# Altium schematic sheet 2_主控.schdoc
size 431 x 309 mm; Symbol: Sheet-Symbol_A3; Device: Sheet-Symbol_A3; Company: 嘉立创EDA; Version: V1.0; Page Size: A3; @Project Name: 基于stm32和ttp233的触摸键盘; @Page Count: 3; @Update Date: 2024-11-03; @Create Date: 2024-11-03; @Schematic Name: Schematic1_1; @Page No: 2; @Page Name: 主控; Title Block Position: 3; Width: 1170; Height: 825; Region Start: 1; X Region Count: 6; Y Region Count: 4; Blade Width: 10; @Board Name: Board1; @Create Time: 21:01:00; @Update Time: 21:01:07
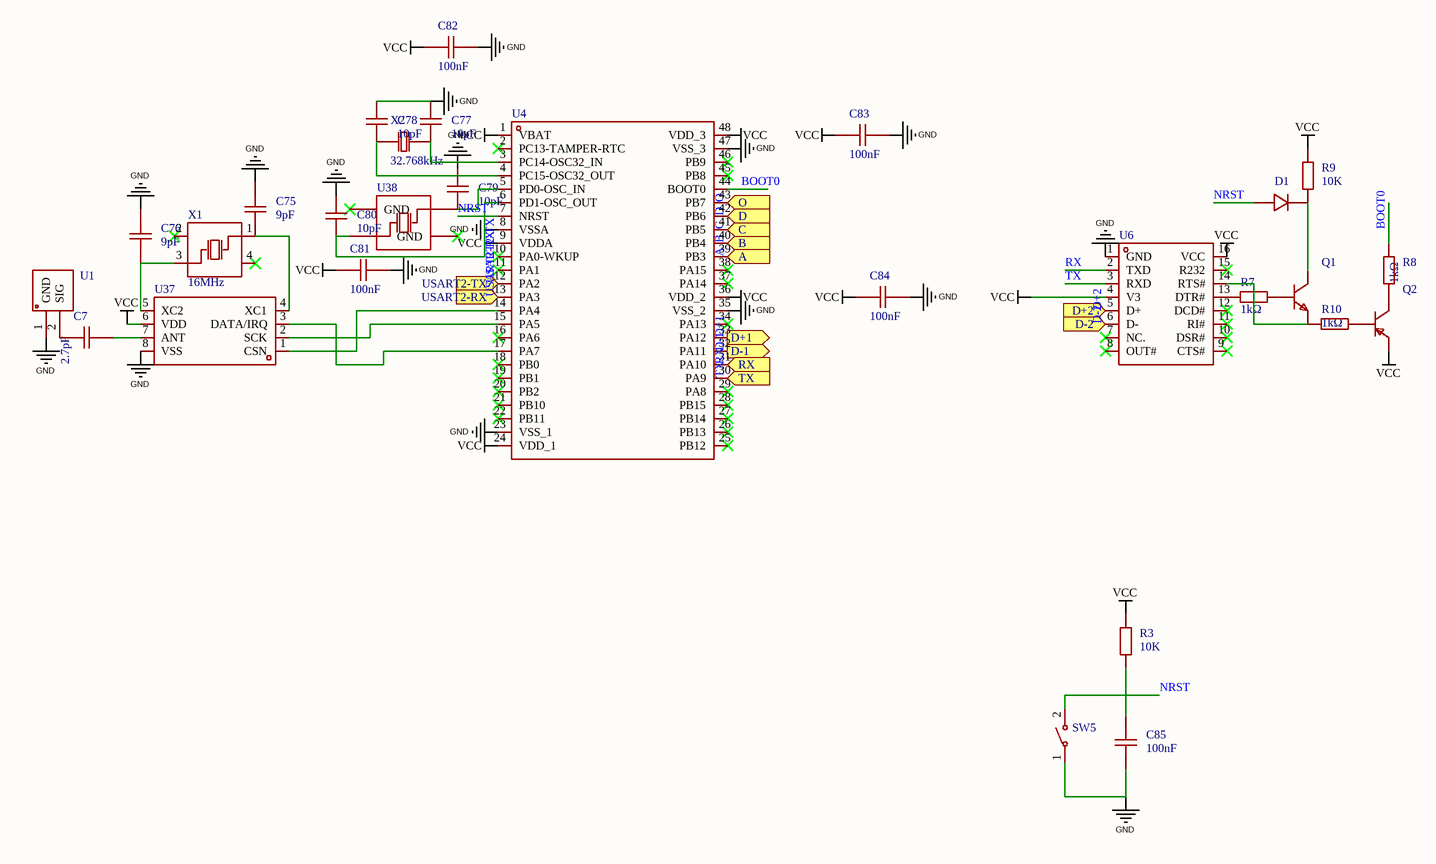
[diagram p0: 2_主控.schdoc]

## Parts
C7  2.7pF  [C0603]
C75  9pF  [C0603]
C76  9pF  [C0603]
C77  10pF  [C0603]
C78  10pF  [C0603]
C79  10pF  [C0603]
C80  10pF  [C0603]
C81  100nF  [C0603]
C82  100nF  [C0603]
C83  100nF  [C0603]
C84  100nF  [C0603]
C85  100nF  [C0603]  (value not drawn)
D1  1N4148W  [SOD-123F_L2.7-W1.6-LS3.8-RD]  (value not drawn)
Q1  S8050 J3Y  [SOT-23-3_L3.0-W1.7-P0.95-LS2.9-BR]  (value not drawn)
Q2  S8550-2TY 800MA  [SOT-23-3_L2.9-W1.6-P1.90-LS2.8-BR]  (value not drawn)
R3  10K  [R0603]  (value not drawn)
R7  1kΩ  [R0603]
R8  1kΩ  [R0603]
R9  10K  [R0603]  (value not drawn)
R10  1kΩ  [R0603]
SW5  TS-1088R-02526  [SW-SMD_L3.9-W3.0-P4.45]  (value not drawn)
U1  板载天线  [板载天线]  (value not drawn)
U4  STM32F103C8T6  [LQFP-48_L7.0-W7.0-P0.50-LS9.0-BL]  (value not drawn)
U6  CH340C  [SOP-16_L10.0-W3.9-P1.27-LS6.0-BL]  (value not drawn)
U37  Ci24R1  [SOIC-8_L4.9-W3.9-P1.27-LS6.0-BL]  (value not drawn)
U38  SMD_3225-8MHz  [CRYSTAL-SMD_4P-L3.2-W2.5-BL]  (value not drawn)
X1  16MHz  [OSC-SMD_4P-L3.2-W2.5-BL]
X2  32.768kHz  [FC-135R_L3.2-W1.5]

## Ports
A (in), B (in), C (in), D (in), D+1 (out), D+2 (in), D-1 (out), D-2 (in), O (in), RX (in), TX (in), USART2-RX (in), USART2-TX (in)

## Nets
GND: C75.2 C76.1 C77.2 C78.2 C79.2 C80.2 C81.1 C82.1 C83.1 C84.1 C85.1 SW5.1 U1.1(GND) U4.8(VSSA) U4.23(VSS_1) U4.35(VSS_2) U4.47(VSS_3) U6.1(GND) U37.8(VSS)
VCC: C81.2 C82.2 C83.2 C84.2 Q2.2(E) R3.2 R9.2 U4.1(VBAT) U4.9(VDDA) U4.24(VDD_1) U4.36(VDD_2) U4.48(VDD_3) U6.4(V3) U6.16(VCC) U37.6(VDD)
A: U4.39(PB3) ; port A
B: U4.40(PB4) ; port B
BOOT0: R8.2 U4.44(BOOT0)
C: U4.41(PB5) ; port C
D: U4.42(PB6) ; port D
D+1: U4.33(PA12) ; port D+1
D+2: U6.5(D+) ; port D+2
D-1: U4.32(PA11) ; port D-1
D-2: U6.6(D-) ; port D-2
NRST: C85.2 D1.2(A) R3.1 SW5.2 U4.7(NRST)
O: U4.43(PB7) ; port O
RX: U4.31(PA10) U6.2(TXD) ; port RX
TX: U4.30(PA9) U6.3(RXD) ; port TX
USART2-RX: U4.13(PA3) ; port USART2-RX
USART2-TX: U4.12(PA2) ; port USART2-TX
NetC7_1: C7.1 U37.7(ANT)
NetC7_2: C7.2 U1.2(SIG)
NetC75_1: C75.1 U37.4(XC1) X1.1(OSC1)
NetC76_2: C76.2 U37.5(XC2) X1.3(OSC2)
NetC77_1: C77.1 U4.3(PC14-OSC32_IN) X2.1
NetC78_1: C78.1 U4.4(PC15-OSC32_OUT) X2.2
NetC79_1: C79.1 U4.5(PD0-OSC_IN) U38.1(OSC1)
NetC80_1: C80.1 U4.6(PD1-OSC_OUT) U38.3(OSC2)
NetD1_1: D1.1(K) Q1.3(C) R9.1
NetQ1_1: Q1.1(B) R7.2
NetQ1_2: Q1.2(E) R10.1 U6.14(RTS#)
NetQ2_1: Q2.1(B) R10.2
NetQ2_3: Q2.3(C) R8.1
NetR7_1: R7.1 U6.13(DTR#)
NetU4_14: U4.14(PA4) U37.1(CSN)
NetU4_15: U4.15(PA5) U37.2(SCK)
NetU4_17: U4.17(PA7) U37.3(DATA/IRQ)

Not connected (* = marked no-connect by the designer): U4 2(PC13-TAMPER-RTC)* 10(PA0-WKUP)* 11(PA1)* 16(PA6)* 18(PB0)* 19(PB1)* 20(PB2)* 21(PB10)* 22(PB11)* 25(PB12)* 26(PB13)* 27(PB14)* 28(PB15)* 29(PA8)* 34(PA13)* 37(PA14)* 38(PA15)* 45(PB8)* 46(PB9)*; U6 7(NC.)* 8(OUT#)* 9(CTS#)* 10(DSR#)* 11(RI#)* 12(DCD#)* 15(R232)*; U38 2(GND)* 4(GND)*; X1 2(GND)* 4(GND)*

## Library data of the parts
C7 = 2.7pF(2R7) ±0.25pF 50V: 容值:2.7pF;额定电压:50V;材质(温度系数):-;; Manufacturer: SAMSUNG(三星); Symbol: 2.7PF(2R7)-±0.25PF-50V; Add into BOM: yes; Voltage Rated: 50V
C75 C76 = CC0603CRNPO9BN9R0: 容值:9pF;额定电压:50V;材质(温度系数):NP0;; Manufacturer: YAGEO(国巨); Add into BOM: yes; Voltage Rated: 50V; Temperature Coefficient: NP0
C77-C80 = CL10C100JB8NNNC: 容值:10pF;精度:±5%;额定电压:50V;材质(温度系数):C0G;; Manufacturer: SAMSUNG(三星); Add into BOM: yes; Tolerance: ±5%; Voltage Rated: 50V; Temperature Coefficient: C0G
C81-C84 = CC0603KRX7R9BB104: 容值:100nF;精度:±10%;额定电压:50V;材质(温度系数):X7R;; Manufacturer: YAGEO(国巨); Add into BOM: yes; Tolerance: ±10%; Voltage Rated: 50V; Temperature Coefficient: X7R
C85 = CAP_0603: Symbol: CapAcitance; Convert to PCB: yes
D1 = 1N4148W_C81598: 二极管配置:独立式;正向压降(Vf):1V@50mA;直流反向耐压(Vr):75V;平均整流电流(Io):150mA;功率:400mW;反向恢复时间(trr):4ns;; Manufacturer: ST(先科); Add into BOM: yes; Diode Configuration: 独立式; Reverse Voltage (Vr): 75V; Average Rectified Current (Io): 150mA; Power Dissipation: 400mW; Reverse Leakage Current: 1uA@75V; Reverse Recovery Time (trr): 4ns
Q1 = S8050 J3Y_C2146: 晶体管类型:NPN;集电极电流(Ic):500mA;集射极击穿电压(Vceo):25V;功率(Pd):300mW;直流电流增益(hFE@Ic,Vce):200@50mA,1V;; Manufacturer: CJ(江苏长电/长晶); Symbol: S8050_C2146; Add into BOM: yes; Transistor Type: NPN; Collector Current (Ic): 500mA; Collector-Emitter Breakdown Voltage (Vceo): 25V; Power Dissipation (Pd): 300mW; Transition Frequency (fT): 150MHz; Collector Cut-Off Current (Icbo): 100nA; Collector-Emitter Saturation Voltage (VCE(sat)@Ic,Ib): 600mV@500mA,50mA
Q2 = S8550-2TY 800MA: Manufacturer: IDCHIP(英锐芯); Add into BOM: yes
R3 R9 = Res_0603: Symbol: 电阻; Convert to PCB: yes
R7 R8 R10 = 0603WAF1001T5E: 电阻类型:厚膜电阻;阻值:1kΩ;精度:±1%;功率:100mW;最大工作电压:75V;温度系数:±100ppm/℃;; Manufacturer: UNI-ROYAL(厚声); Add into BOM: yes; Tolerance: ±1%; Power(Watts): 100mW; Overload Voltage (Max): 75V
SW5 = TS-1088R-02526: 电路结构:单刀单掷;按钮形状:圆形按钮;安装方式:立贴;开关长度:3.9mm;开关宽度:2.93mm;开关高度:2.5mm;触点电流:50mA;额定电压(DC):12V;带灯:-;机械寿命:-;; Manufacturer: XUNPU(讯普); Add into BOM: yes; Circuit: 单刀单掷; Actuator Style: 圆形按钮; Switch Length: 3.9mm; Switch Width: 2.93mm; Switch Height: 2.5mm; Contact Current: 50mA; Voltage Rating (DC): 12V
U1 = 板载天线: Add into BOM: yes
U4 = STM32F103C8T6: CPU内核:ARM-M3;程序存储容量:64KB;RAM总容量:20KB;GPIO端口数量:37;工作电压范围:2V~3.6V;CPU最大主频:72MHz;程序存储器类型:FLASH;; Manufacturer: ST(意法半导体); Add into BOM: yes; CPU Core: ARM-M3; Program Storage Size: 64KB; RAM Size: 20KB; GPIO Ports Number: 37; CPU Maximum Speed: 72MHz; Program Memory Type: FLASH; ADC (Bit): 12bit; Universal Serial Bus: 有; Peripheral/Function: 看门狗；DMA；看门狗；温度传感器
U6 = CH340C: 应用功能:收发器;接口协议:USB 2.0;数据速率:2Mbps;; Manufacturer: WCH(南京沁恒); Add into BOM: yes; Applications Function: 收发器; Protocol: USB 2.0; Supply Voltage: 3.3V；5V; Data Rate: 2Mbps
U37 = Ci24R1: 频率范围:2.4GHz~2.525GHz;接口:SPI;应用领域:ISM;数据速率:2Mbps;灵敏度:-80dBm;典型应用频率:2.4GHz;; Manufacturer: 南京中科微; Add into BOM: yes; Interface: SPI; Operating Voltage: 2.1V~3.6V; Output Power: 11dBm; Data Rate: 2Mbps; Current Of Transmitting: 18mA; Sensitivity: -80dBm; Receive Current: 20mA; Typical Application Frequency: 2.4GHz
U38 = SMD_3225-8MHz: Add into BOM: yes
X1 = X322516MLB4SI: 晶振类型:贴片晶振;频率:16MHz;常温频差:±10ppm;外接负载电容:9pF;频率稳定度(全温):±20ppm;; Manufacturer: YXC(扬兴晶振); Add into BOM: yes; Crystal Type: 贴片晶振; Normal temperature Frequency Tolerance: ±10ppm; External load capacitor: 9pF; Frequency Stability(Full temperature range): ±20ppm
X2 = Q13FC13500004_C32346: 晶振类型:贴片晶振;频率:32.768kHz;常温频差:±20ppm;外接负载电容:12.5pF;; Manufacturer: EPSON(爱普生); Symbol: Q13FC1350000400; Add into BOM: yes; Crystal Type: 贴片晶振; Normal temperature Frequency Tolerance: ±20ppm; External load capacitor: 12.5pF; Equivalent Series Resistance (ESR): 70kΩ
